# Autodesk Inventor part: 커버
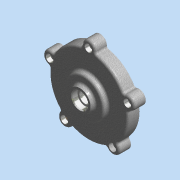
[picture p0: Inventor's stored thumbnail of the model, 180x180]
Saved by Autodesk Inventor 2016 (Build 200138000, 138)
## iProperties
Created: 2015-11
Part Number: 커버
Document SubType Name: 모델링
Designer: mdu
Material: 알루미늄 6061
Density: 2.71 g/cm^3
Mass: 201.189 g
Surface Area: 286.328 cm^2
Volume: 74.2394 cm^3
Appearance: 알루미늄 캐스트
변환 표준: STEP AP214IS
파일 이름: C:\Users\SeoGD\Desktop\?쒗뿕\而ㅻ쾭-1.stp
전처리기: Build: 253, Release: 2010 SP1 - Date: Wed 07/29/2009
전송 단위: 밀리미터
불확실성: 0.01
Author: mdu
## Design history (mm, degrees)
sketch "스케치1"
  geometry: L1 (0, 0)-(0, 26); L2 (50, 0)-(50, 15); L3 (50, 15)-(25, 15); L4 (25, 15)-(25, 21); L5 (25, 21)-(15, 21); L6 (15, 21)-(13.66, 26); L7 (13.66, 26)-(10, 26); L8 (50, 0)-(45, 0); L9 (45, 0)-(45, 10); L10 (45, 10)-(14.5, 10); L11 (14.5, 10)-(13.266, 3); L12 (13.266, 3)-(11, 3); L13 (11, 3)-(11, 16); L14 (11, 16)-(7.5, 16); L15 (7.5, 16)-(7.5, 19); L16 (7.5, 19)-(10, 19); L17 (10, 19)-(10, 26)
  constraints: 34 end point, 10 parallel, 2 perpendicular, 2 point on line, 1 vertical
  dimensions: "d11" = 100 diameter of L2 L1; "d12" = 22 diameter of L13 L1; "d13" = 90 diameter of L9 L1; "d14" = 15 distance between parallel lines of L3 L8; "d15" = 10 distance between parallel lines of L8 L10; "d16" = 29 diameter of L10.end L1; "d17" = 100 deg angle of L11 L10; "d18" = 7 distance between parallel lines of L12 L10; "d19" = 13 distance between parallel lines of L14 L12; "d20" = 3 distance between parallel lines of L16 L14; "d21" = 15 diameter of L15 L1; "d22" = 20 diameter of L17 L1; "d23" = 30 diameter of L5.end L1; "d24" = 6 distance between parallel lines of L5 L3; "d25" = 50 diameter of L4 L1; "d26" = 105 deg angle of L5 L6; "d50" = 26 distance of L1.start L1.end
revolve "회전1" sketch "스케치1" stored, may be unused: angle "d27" = 90 deg
sketch "스케치2" dims "d29" = 104
  geometry: A1 r 8.5 centre (0, 52) between (8.074, 49.344) and (-8.074, 49.344); A2 r 50 centre (0, 0) between (-8.074, 49.344) and (8.074, 49.344) reference; 2 further points
  constraints: 4 point on circle, 2 vertical alignment, 1 centre point, 1 coincident, 2 other
  dimensions: "d28" = 17 diameter of A1
extrude "돌출1" join sketch "스케치2" stored distance "d30" = 10; taper "d31" = 0 deg
fillet "모깎기3" dims "d32" = 3
fillet "모깎기4" dims "d45" = 3, "d46" = 0.2
chamfer "모따기1" distance "d47" = 1; stored, may be unused: second distance "d48" = 2, angle "d49" = 45 deg
hole "구멍2" diameter "d38" = 5.5; stored, may be unused: countersink angle "d42" = 90 deg, drill point angle "d44" = 118 deg; dims "d36" = 10, "d37" = 10, "d39" = 6, "d40" = 9.5, "d41" = 5.4, "d43" = 8
node "솔리드1"
node "솔리드 본체"
node "곡면 본체"
pattern_circular "원형 패턴1" dims angle "d34" = 360 deg
pattern_circular "원형 패턴2" dims angle "d52" = 360 deg
node "솔리드2"
